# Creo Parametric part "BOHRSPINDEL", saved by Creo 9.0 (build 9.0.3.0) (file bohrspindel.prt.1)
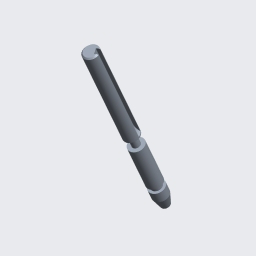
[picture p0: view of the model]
Units: millimeter Kilogram Sec (mmKs); MM, KILOGRAM, SECS
Materials in the file: STAHL

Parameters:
  WERKSTOFF = "Stahl"
  ERSTELLER = "ARINDA"
  BENENNUNG = "XXX"
  TEILETYP = "K"
  PTC_MASTER_MATERIAL = "STAHL"

Other parameters: MASSE

Created from: ARINDA_STARTTEIL.PRT

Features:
  1. coordinate system
  2. datum plane "RECHTS_Y-Z"
  3. datum plane "OBEN_X-Z"
  4. datum plane "VORNE_X-Y"
  5. datum axis
  6. datum axis
  7. datum axis
  8. datum point "PNT0"
  9. revolve "Drehen 1"
  10. revolved cut "Drehen 2"
  11. extruded cut "Profil 1"
  12. cut
  13. chamfer "Fase 1"
  14. chamfer "Fase 2"
  15. round "Rundung 1"

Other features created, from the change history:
  coordinate system "CS1"

Other named items: GRUNDKÖRPER, NUT-HEBEL, NUT-RIEMENSCHEIBE, F0_5, BOHRFUTTER, F5X15, R0_5, A_X, A_Y, A_Z, CS0

Layers: 01_ACHSEN_STD, 01_EBENEN_STD, 01_KOORDSYS_STD, 01_PUNKTE_STD, VOLUMENGEOMETRIE

Surfaces: 9 plane, 7 cylinder, 3 cone, 2 torus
